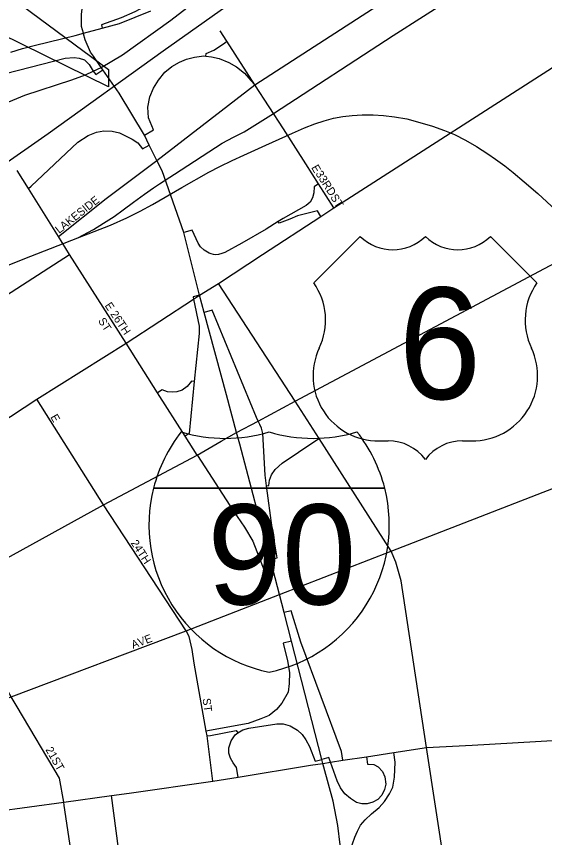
# Model space of a CAD drawing. Extents: x 2139079 to 2262683, y 1235796 to 1334992.
# Drawn here: x 2194033 to 2197328, y 1277243 to 1282370 of the extents above; entities that cross this region are included whole.
import ezdxf

# ---------------------------------------------------------------- set-up
doc = ezdxf.new("R2010")
doc.units = 0
for name, color, linetype in [('GM_X_Airport_Class_1', 7, 'Continuous'), ('GM_X_City_Street', 7, 'Continuous'), ('GM_X_City_Street_Text', 7, 'Continuous'), ('GM_X_Interchange_Ramps', 7, 'Continuous'), ('GM_X_Interstate_Location', 7, 'Continuous'), ('GM_X_Interstate_Route', 7, 'Continuous'), ('GM_X_Interstate_Shield', 7, 'Continuous'), ('GM_X_Rail_Line', 7, 'Continuous'), ('GM_X_State_Route', 7, 'Continuous'), ('GM_X_US_Location', 7, 'Continuous'), ('GM_X_US_Route', 7, 'Continuous'), ('GM_X_US_Shield', 7, 'Continuous')]:
    doc.layers.add(name, color=color, linetype=linetype)

msp = doc.modelspace()

# ---------------------------------------------------------------- linework, layer by layer
at = {"layer": 'GM_X_Airport_Class_1'}
msp.add_lwpolyline([(2194071.4, 1282435.3), (2194606.8, 1282039.4), (2194606.8, 1281929.9), (2193260.5, 1282593.4), (2193260.5, 1282263.2), (2193200.4, 1281930.7), (2193572.9, 1281596.6), (2193567.1, 1281459), (2193159, 1281711.9), (2193140.2, 1281637.8)], dxfattribs=at)
at = {"layer": 'GM_X_City_Street'}
for points in [[(2193289.3, 1281359), (2193299.7, 1281367.3), (2193552, 1281546.9), (2193802.9, 1281728.2), (2193935.7, 1281815.7), (2194084.6, 1281878.9), (2194378.3, 1281974.7), (2194463.9, 1282006.1), (2194512.4, 1282028.8), (2194561, 1282051.6), (2194694.7, 1282130.5), (2194996.1, 1282346.7), (2195257.9, 1282550.9), (2195383.5, 1282693.6), (2195668, 1283075.6), (2195903.1, 1283394.7), (2196027, 1283536.1), (2196119.5, 1283633.9), (2196406.7, 1283843.3), (2197904.1, 1284893.8)], [(2195567.4, 1280882.4), (2195932.5, 1281121.6), (2196013.9, 1281174.9), (2197516.4, 1282140.7), (2200878.3, 1284302)], [(2194295.9, 1280994.8), (2194592.7, 1281234.1), (2194909, 1281470.8), (2195521.2, 1281942), (2197025, 1282915.9)], [(2195521.2, 1281942), (2195345.6, 1282215.1), (2195304.2, 1282279.5)], [(2195838.7, 1281448.8), (2195698.6, 1281667.9), (2195521.2, 1281942)], [(2194295.9, 1280994.8), (2194107.6, 1281295.1), (2194037, 1281407.6)], [(2196013.9, 1281174.9), (2195917.7, 1281325.3), (2195838.7, 1281448.8)], [(2194362.9, 1280882.8), (2194295.9, 1280994.8)], [(2191143.3, 1278804.7), (2192038.6, 1279382.6), (2192253.8, 1279521.5), (2194362.9, 1280882.8)], [(2191484.2, 1278250.3), (2191491.2, 1278255.1), (2192389.5, 1278830.9), (2192631.9, 1278986.3), (2193257.9, 1279387.5), (2194159.3, 1279980.2), (2194716.7, 1280330.3), (2195137.4, 1280604.8), (2195175.8, 1280629.9), (2195293.5, 1280703), (2195567.4, 1280882.4)], [(2194913.7, 1280019.7), (2194716.7, 1280330.3), (2194362.9, 1280882.8)], [(2192078.6, 1277394.3), (2192139, 1277429.1), (2192255.8, 1277493.6), (2192381.1, 1277540.8), (2193054.4, 1277782.2), (2193377.5, 1277898), (2194000, 1278121.1), (2195091.4, 1278534.1), (2195674.4, 1278761.3), (2196370.6, 1279030.8), (2198889.4, 1280010.3), (2200879.8, 1280784.3)], [(2196707.8, 1277046.4), (2196591.7, 1277805.3), (2196433.7, 1278846.3), (2196400.2, 1278961.4), (2196370.6, 1279030.8), (2195921, 1279734.8), (2195772.2, 1279967.9), (2195293.5, 1280703)], [(2195085, 1279749.4), (2194913.7, 1280019.7)], [(2195091.4, 1278534.1), (2194574.9, 1279320.4), (2194159.3, 1279980.2)], [(2195160, 1279631.1), (2195085, 1279749.4)], [(2194037.4, 1278058.4), (2194000, 1278121.1), (2193613.8, 1278789.6), (2193257.9, 1279387.5)], [(2195216.4, 1277907.7), (2195216.4, 1277907.7), (2195140.9, 1278332.3), (2195128.5, 1278417.9), (2195110.6, 1278498.2), (2195091.4, 1278534.1)], [(2194331.1, 1277443), (2194328.1, 1277463), (2194302.1, 1277614.2), (2194037.4, 1278058.4)], [(2195258.7, 1277595.4), (2195222, 1277877), (2195216.4, 1277907.7)], [(2194722.5, 1276764.2), (2194625.3, 1277504.8)], [(2194441.3, 1276707.4), (2194331.1, 1277443)]]:
    msp.add_lwpolyline(points, dxfattribs=at)
at = {"layer": 'GM_X_Interchange_Ramps'}
for points in [[(2194880.4, 1282918), (2194901.7, 1282887.9), (2194995, 1282951.9), (2195052.2, 1282970), (2195105.3, 1282971.6), (2195158.2, 1282953.7), (2195192.3, 1282921), (2195215.9, 1282875.3), (2195225.1, 1282819.7), (2195215.6, 1282768.7), (2195193.7, 1282724.6), (2195137.1, 1282660.6), (2195062, 1282589.7), (2194987.6, 1282529), (2194913.2, 1282479.7), (2194834.2, 1282431.3), (2194771, 1282399.5), (2194685.7, 1282360.3), (2194562.9, 1282316.6), (2194568.1, 1282297.4)], [(2195214, 1282121.5), (2195216.2, 1282138.3), (2195264.9, 1282158.8), (2195330, 1282203.6), (2195345.6, 1282215.1)], [(2194831.2, 1281628.5), (2194887, 1281661.1), (2194857.7, 1281736.7), (2194853.5, 1281804.1), (2194865.5, 1281867.8), (2194888.2, 1281921.6), (2194918.1, 1281971.8), (2194959.6, 1282022.8), (2195002, 1282057.6), (2195049.8, 1282085.2), (2195094.8, 1282103), (2195144.3, 1282116.2), (2195201.8, 1282123.2), (2195214, 1282121.5), (2195250.3, 1282116.6), (2195297, 1282106.5), (2195357.1, 1282082.9), (2195406.4, 1282055.7), (2195455.6, 1282015), (2195495.9, 1281970.9), (2195521.2, 1281942)], [(2193361.5, 1281862.5), (2193380.8, 1281825.6), (2193507, 1281880.8), (2193627.7, 1281924), (2193743.3, 1281956.9), (2194336.8, 1282108.6), (2194393, 1282114.3), (2194424.6, 1282110.1), (2194457.7, 1282098), (2194485.5, 1282069.1), (2194512.4, 1282028.8), (2194527.1, 1282007), (2194571.9, 1282035.8)], [(2194107.6, 1281295.1), (2194124.3, 1281310.8), (2194415.8, 1281584.3), (2194479.8, 1281626.2), (2194532.9, 1281646.6), (2194577.9, 1281655.4), (2194629.1, 1281654.3), (2194675.8, 1281644.1), (2194713.4, 1281625.1), (2194754.7, 1281604.2), (2194789.6, 1281579.8), (2194818.2, 1281542.8), (2194860.9, 1281566.7)], [(2195917.7, 1281325.3), (2195889.6, 1281306.2), (2195888.6, 1281268.5), (2195879.4, 1281237.1), (2195865.8, 1281210.2), (2195841.4, 1281188.8), (2195697.3, 1281108.6), (2195666.2, 1281088.7), (2195591, 1281040.8), (2195438.7, 1280953.5), (2195332.7, 1280896.8), (2195314.6, 1280889.1), (2195292.8, 1280883.3), (2195276.9, 1280882.2), (2195261.4, 1280883.4), (2195246.9, 1280887.4), (2195234.4, 1280892.5), (2195203.1, 1280910.7), (2195181.6, 1280930.5), (2195166.4, 1280953.9), (2195129, 1281035.9), (2195077.2, 1281021.3)], [(2195932.5, 1281121.6), (2195910.5, 1281156.1), (2195786.3, 1281124.3), (2195737.7, 1281103.9), (2195672.9, 1281078.2), (2195666.2, 1281088.7)], [(2195175.8, 1280629.9), (2195134.4, 1280619.2), (2195137.4, 1280604.8), (2195172.2, 1280435.5), (2195172, 1280390.6), (2195142.6, 1280090.8), (2195110.7, 1279766.5), (2195085, 1279749.4)], [(2195540.9, 1279843.6), (2195529.6, 1279864.9), (2195254.4, 1280535.8), (2195204.7, 1280522.2)], [(2195142.6, 1280090.8), (2195124.8, 1280092.6), (2195098.6, 1280058.6), (2195067, 1280036.3), (2195032.8, 1280026.5), (2195004, 1280023.1), (2194974.4, 1280026.8), (2194942.1, 1280038.6), (2194913.7, 1280019.7)], [(2195616.6, 1278979.2), (2195659, 1278989.4), (2195627.5, 1279176.4), (2195594, 1279438.8), (2195584.9, 1279506.4), (2195569.9, 1279766.1), (2195561.7, 1279799.2), (2195551.9, 1279822.8), (2195540.9, 1279843.6)], [(2195594, 1279438.8), (2195608, 1279440.7), (2195611.8, 1279474.8), (2195623.6, 1279507.1), (2195648, 1279542), (2195690.4, 1279581.3), (2195895, 1279718.7), (2195921, 1279734.8)], [(2195160, 1279631.1), (2195161.9, 1279628.1), (2195387.1, 1279280), (2195455.8, 1279180), (2195506.7, 1279093.5), (2195582.2, 1278900), (2195634.1, 1278913.3)], [(2196069.7, 1277725.4), (2196060.6, 1277780), (2195808.2, 1278462.3), (2195746.2, 1278659.3), (2195703.1, 1278648.8)], [(2195749.1, 1278469), (2195697.9, 1278456.5), (2195723.5, 1278346.8), (2195735.7, 1278273), (2195734.5, 1278203.8), (2195728, 1278150.9), (2195689, 1278082.8), (2195654.7, 1278041.6), (2195609.6, 1278005.9), (2195558.3, 1277984.6), (2195478.2, 1277955.3), (2195237.1, 1277910.7), (2195216.4, 1277907.7)], [(2195416.4, 1277620.9), (2195406.8, 1277680.7), (2195385.4, 1277709.6), (2195368.4, 1277738.4), (2195357.8, 1277770.8), (2195357.9, 1277802.3), (2195371.6, 1277847.1), (2195397, 1277883.8), (2195415, 1277897.2), (2195445.4, 1277916), (2195483.4, 1277925.7), (2195657, 1277952.7), (2195697.4, 1277952.5), (2195740.7, 1277940), (2195787.1, 1277914.4), (2195815.9, 1277887.2), (2195837.5, 1277853.6), (2195860.3, 1277811.5), (2195897.7, 1277720.6), (2195937.6, 1277730.8)], [(2195222, 1277877), (2195244.2, 1277880.1), (2195404.3, 1277911.7), (2195415, 1277897.2)], [(2196054.4, 1277033.7), (2196104.9, 1277035), (2196109.6, 1277097.9), (2196118, 1277158.9), (2196129, 1277202.9), (2196143.5, 1277245.1), (2196160.8, 1277283.6), (2196178.9, 1277319.4), (2196207.8, 1277354.3), (2196248.4, 1277390.1), (2196296.3, 1277431.2), (2196328.8, 1277468.7), (2196361.3, 1277515.3), (2196380.4, 1277557.5), (2196391.5, 1277619.4), (2196396.4, 1277713.7), (2196386.8, 1277773.9)], [(2196216.8, 1277747.9), (2196223.8, 1277701.9), (2196262.4, 1277698.2), (2196289.3, 1277684.6), (2196317, 1277654.8), (2196332.2, 1277622.4), (2196338.2, 1277576.5), (2196330, 1277542.4), (2196312.8, 1277508.4), (2196287.5, 1277480.6), (2196256.9, 1277464.6), (2196221.8, 1277453.1), (2196188.5, 1277454.2), (2196154.4, 1277462.4), (2196116.8, 1277485.9), (2196081.9, 1277514.9), (2196054.2, 1277553.6), (2196033.2, 1277596.6), (2195992.7, 1277713.6), (2195982.7, 1277742.3), (2195937.6, 1277730.8)]]:
    msp.add_lwpolyline(points, dxfattribs=at)
at = {"layer": 'GM_X_Interstate_Route'}
for points in [[(2194451.2, 1282262), (2194450.3, 1282265.4), (2194439.2, 1282308), (2194437.7, 1282382.7), (2194448.6, 1282466.7), (2194479.7, 1282555.4), (2194529.5, 1282630.1), (2194545.9, 1282646.1)], [(2194513.1, 1282120.9), (2194495.3, 1282146.8), (2194461, 1282224), (2194451.2, 1282262)], [(2195342.9, 1280008.1), (2195204.7, 1280522.2), (2195175.8, 1280629.9), (2195077.2, 1281021.3), (2194941.8, 1281405.5), (2194909, 1281470.8), (2194860.9, 1281566.7), (2194831.2, 1281628.5), (2194672.6, 1281890.1), (2194571.9, 1282035.8), (2194561, 1282051.6), (2194513.1, 1282120.9)], [(2195425.6, 1279699.6), (2195406.6, 1279771.5), (2195342.9, 1280008.1)], [(2195950.6, 1277681.7), (2195943.9, 1277706.2), (2195937.6, 1277730.8), (2195749.1, 1278469), (2195703.1, 1278648.8), (2195674.4, 1278761.3), (2195634.1, 1278913.3), (2195616.6, 1278979.2), (2195425.6, 1279699.6)], [(2196049.8, 1276973.5), (2196054.4, 1277033.7), (2196051.8, 1277197.3), (2196038.3, 1277318.3), (2196008.7, 1277470.1), (2195950.6, 1277681.7)]]:
    msp.add_lwpolyline(points, dxfattribs=at)
at = {"layer": 'GM_X_Interstate_Shield'}
for p, q in [((2194888, 1279424.5), (2196330.8, 1279424.5)), ((2196330.8, 1279424.5), (2194888, 1279424.5)), ((2196330.8, 1279424.5), (2194888, 1279424.5))]:
    msp.add_line(p, q, dxfattribs=at)
for centre, start, end in [((2195796.9, 1279194.6), 141.669, 165.8066), ((2195335.5, 1280672.7), 253.0091, 286.9909), ((2195883.4, 1280672.7), 253.0091, 286.9909), ((2195421.9, 1279194.6), 14.1934, 38.331), ((2195796.9, 1279194.6), 165.8066, 258.463), ((2195421.9, 1279194.6), 281.537, 14.1934)]:
    msp.add_arc(centre, 937.5, start, end, dxfattribs=at)
at = {"layer": 'GM_X_Rail_Line'}
for points in [[(2188798.9, 1277974.5), (2189752.1, 1278588.8), (2190639.6, 1279116), (2192678, 1280555.1), (2194231.5, 1281639.3), (2194948.6, 1282154.6), (2195509, 1282554.5), (2195871.7, 1282810.1), (2196378.5, 1283156.3), (2197087.3, 1283630.4), (2199383.9, 1285076.5), (2199860.7, 1285394.8)], [(2194416.4, 1280986.7), (2194514.1, 1281040.4), (2194576, 1281078.4), (2194641.6, 1281120.9), (2194698.3, 1281162.7), (2194762.5, 1281209.7), (2194832.6, 1281260.4), (2194887, 1281299.9), (2194925.8, 1281323.8), (2195019.7, 1281384.9), (2195316.5, 1281578.8), (2195387.4, 1281616.8), (2195453.7, 1281648.9), (2195636.5, 1281764.5), (2196384.2, 1282250.1), (2196761.5, 1282494.8), (2197362, 1282889.7)], [(2194416.4, 1280986.7), (2194619.3, 1281066.5), (2194721.4, 1281112.7), (2194804.2, 1281154.5), (2194881, 1281194.8), (2195065.2, 1281301.4), (2195233.8, 1281396.9), (2195300.9, 1281433.4), (2195378.4, 1281470.7), (2195450.8, 1281503.5), (2195588, 1281565.4), (2195755, 1281641.5), (2195831.1, 1281674.3), (2195895.2, 1281698.9), (2195952.6, 1281718.3), (2196010.8, 1281733.9), (2196069.7, 1281744.4), (2196127.9, 1281751.8), (2196189.8, 1281755.6), (2196259.1, 1281755.6), (2196324, 1281751.1), (2196391.1, 1281742.9), (2196469.4, 1281729.5), (2196550.7, 1281708.6), (2196628.3, 1281684.7), (2196704.3, 1281657.9), (2196767, 1281631.8), (2196834.1, 1281598.2), (2196903.5, 1281558.7), (2196974.3, 1281512.4), (2197022.8, 1281478.9), (2197079.4, 1281437.9), (2197132.4, 1281394.6), (2197201.7, 1281337.2), (2197285.3, 1281264.1), (2197511.2, 1281056.8)], [(2188798.9, 1277881.4), (2189757.9, 1278481.3), (2190617.3, 1279020.4), (2191767.2, 1279829.6), (2191989.8, 1279978), (2192129.9, 1280056.3), (2192326.4, 1280152.7), (2192459.3, 1280209.9), (2192568.2, 1280252.3), (2192695.5, 1280304), (2194123.4, 1280872.7), (2194416.4, 1280986.7)]]:
    msp.add_lwpolyline(points, dxfattribs=at)
at = {"layer": 'GM_X_State_Route'}
for points in [[(2194152, 1282190.5), (2194398.8, 1282251.4), (2194450.3, 1282265.4), (2194568.1, 1282297.4), (2194675.2, 1282326.5), (2194870.4, 1282405.6)], [(2193997.2, 1282146.1), (2194071.1, 1282170.5), (2194152, 1282190.5)]]:
    msp.add_lwpolyline(points, dxfattribs=at)
at = {"layer": 'GM_X_US_Route'}
for points in [[(2195310.7, 1279716.9), (2195406.6, 1279771.5), (2195540.9, 1279843.6), (2195772.2, 1279967.9), (2198105.6, 1281211.1), (2199508.9, 1281962.3), (2199732.1, 1282082.7), (2199981.1, 1282217.3), (2200240.2, 1282358.1), (2200816.9, 1282682.5), (2200904.1, 1282710.1)], [(2191921.2, 1277613.3), (2192778.4, 1278219.4), (2193058.9, 1278407.8), (2193613.8, 1278789.6), (2194574.9, 1279320.4), (2195160, 1279631.1), (2195310.7, 1279716.9)], [(2196216.8, 1277747.9), (2196386.8, 1277773.9), (2196591.7, 1277805.3), (2196875.6, 1277820), (2197559.1, 1277860), (2197658.4, 1277866.4), (2197757.6, 1277874.4), (2197845.6, 1277877.6), (2197911.4, 1277883.8)], [(2195868.5, 1277694), (2195943.9, 1277706.2), (2195992.7, 1277713.6), (2196069.7, 1277725.4), (2196216.8, 1277747.9)], [(2194736.8, 1277520.8), (2195258.7, 1277595.4), (2195416.4, 1277620.9), (2195868.5, 1277694)], [(2192748.1, 1277242.7), (2193141.7, 1277299.4), (2193469.6, 1277346.7), (2194328.1, 1277463), (2194625.3, 1277504.8), (2194736.8, 1277520.8)]]:
    msp.add_lwpolyline(points, dxfattribs=at)
at = {"layer": 'GM_X_US_Shield'}
for p, q in [((2196178.1, 1280996.2), (2195888.1, 1280706.1)), ((2197280.3, 1280706.1), (2196990.2, 1280996.2)), ((2196294.1, 1279720), (2196352.2, 1279720)), ((2196816.2, 1279720), (2196874.2, 1279720))]:
    msp.add_line(p, q, dxfattribs=at)
for centre, radius, start, end in [((2196381.2, 1281203.3), 290, 225.573, 314.427), ((2196787.2, 1281203.3), 290, 225.573, 314.427), ((2195555.5, 1280473.2), 406.1, 334.5471, 35.0009), ((2197612.9, 1280473.2), 406.1, 144.9991, 205.4529), ((2196289.6, 1280126), 406.1, 154.8319, 270.6383), ((2196878.7, 1280126), 406.1, 269.3617, 25.1681), ((2196352.2, 1279429.9), 290, 36.8699, 90), ((2196816.2, 1279429.9), 290, 90, 143.1301)]:
    msp.add_arc(centre, radius, start, end, dxfattribs=at)

# ---------------------------------------------------------------- texts
at = {"layer": 'GM_X_City_Street_Text'}
for s, rotation, p in [('E', 299.755, (2195870.7, 1281426.5)), ('33RD', 302.7376, (2195896.9, 1281387.4)), ('LAKESIDE', 38.3943, (2194299.1, 1281011.3)), ('ST', 301.6047, (2195989.4, 1281242)), ('E 26TH', 303.6929, (2194581.2, 1280564.7)), ('ST', 302.7321, (2194539.7, 1280469.6)), ('E', 299.755, (2194242.8, 1279868.9)), ('24TH', 303.3094, (2194744.1, 1279081.8)), ('AVE', 20.3197, (2194759.3, 1278421.1)), ('ST', 277.12, (2195194.3, 1278109.8)), ('21ST', 299.7456, (2194212, 1277792.1))]:
    msp.add_text(s, height=50, rotation=rotation, dxfattribs=at).set_placement(p)
at = {"layer": 'GM_X_Interstate_Location'}
for s in ['-', '.', ',']:
    msp.add_text(s, height=1, dxfattribs=at).set_placement((2195609.3, 1279025.6))
msp.add_text('90', height=1, rotation=0, dxfattribs=at).set_placement((2195405, 1278818.6))
at = {"layer": 'GM_X_Interstate_Shield'}
msp.add_text('90', height=625, dxfattribs=at).set_placement((2195224.2, 1278698))
at = {"layer": 'GM_X_US_Location'}
for s in ['0', '/']:
    msp.add_text(s, height=1, dxfattribs=at).set_placement((2196583.9, 1280323.6))
msp.add_text('6', height=1, rotation=0, dxfattribs=at).set_placement((2196483, 1280116.6))
at = {"layer": 'GM_X_US_Shield'}
msp.add_text('6', height=696.1, dxfattribs=at).set_placement((2196416, 1279981))

doc.saveas('drawing.dxf')
